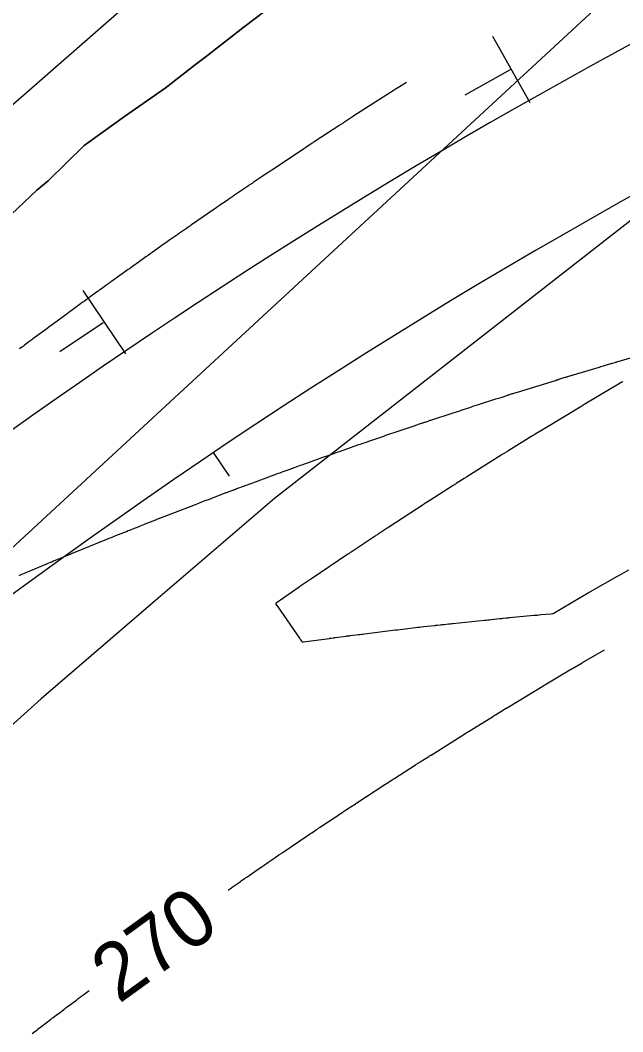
# Model space of a CAD drawing. Extents: x 1710723 to 1713003, y 548603 to 551142.
# Drawn here: x 1711041.1 to 1711104.3, y 549044.7 to 549150.8 of the extents above; entities that cross this region are included whole.
import ezdxf

# ---------------------------------------------------------------- set-up
doc = ezdxf.new("R2010")
doc.units = 0
for name, color, linetype in [('R_Contour Annot', 7, 'Continuous'), ('R_Contours', 7, 'Continuous'), ('R_Horz Alg', 7, 'Continuous'), ('R_Horz Alg Annot', 7, 'Continuous'), ('R_MOT', 7, 'Continuous'), ('R_No Plot', 7, 'Continuous'), ('R_Striping', 7, 'Continuous')]:
    doc.layers.add(name, color=color, linetype=linetype)

msp = doc.modelspace()

# ---------------------------------------------------------------- linework, layer by layer
at = {"layer": 'R_Contours'}
for points in [[(1711081.57, 549144.32), (1711080.41, 549143.58), (1711080.37, 549143.56), (1711080.28, 549143.5), (1711076.06, 549140.8), (1711076.03, 549140.78), (1711075.92, 549140.71), (1711074.98, 549140.1), (1711074.94, 549140.07), (1711074.9, 549140.04), (1711074.86, 549140.02), (1711074.82, 549139.99), (1711074.57, 549139.83), (1711074.49, 549139.78), (1711071.9, 549138.08), (1711071.81, 549138.02), (1711071.72, 549137.96), (1711071.63, 549137.9), (1711071.54, 549137.84), (1711071.18, 549137.61), (1711071.01, 549137.49), (1711070.83, 549137.37), (1711067.51, 549135.16), (1711067.47, 549135.13), (1711067.43, 549135.11), (1711067.38, 549135.08), (1711067.34, 549135.05), (1711067.13, 549134.91), (1711067, 549134.82), (1711066.45, 549134.45), (1711066.34, 549134.38), (1711066.24, 549134.31), (1711066.13, 549134.24), (1711066.03, 549134.16), (1711065.5, 549133.81), (1711065.38, 549133.72), (1711065.26, 549133.64), (1711065.13, 549133.56), (1711065.01, 549133.47), (1711063.54, 549132.48), (1711063.35, 549132.35), (1711063.16, 549132.22), (1711062.96, 549132.08), (1711062.77, 549131.95), (1711062.01, 549131.43), (1711061.82, 549131.3), (1711061.63, 549131.17), (1711061.44, 549131.04), (1711061.25, 549130.91), (1711059.03, 549129.37), (1711058.97, 549129.33), (1711058.91, 549129.29), (1711058.85, 549129.25), (1711058.79, 549129.21), (1711058.49, 549129), (1711058.31, 549128.87), (1711057.86, 549128.56), (1711057.77, 549128.5), (1711057.68, 549128.43), (1711057.58, 549128.37), (1711057.49, 549128.3), (1711056.77, 549127.8), (1711056.62, 549127.69), (1711056.47, 549127.59), (1711056.32, 549127.48), (1711056.17, 549127.37), (1711055.13, 549126.65), (1711054.91, 549126.49), (1711054.69, 549126.33), (1711054.47, 549126.17), (1711054.25, 549126.02), (1711053.3, 549125.34), (1711053.07, 549125.18), (1711052.84, 549125.01), (1711052.61, 549124.85), (1711052.38, 549124.68), (1711050.65, 549123.45), (1711050.57, 549123.39), (1711050.49, 549123.34), (1711050.42, 549123.28), (1711050.34, 549123.23), (1711050.03, 549123), (1711049.87, 549122.89), (1711049.72, 549122.78), (1711049.38, 549122.54), (1711049.3, 549122.48), (1711049.22, 549122.42), (1711049.14, 549122.36), (1711049.05, 549122.3), (1711048.11, 549121.61), (1711047.93, 549121.48), (1711047.75, 549121.35), (1711047.57, 549121.22), (1711047.39, 549121.09), (1711046.68, 549120.57), (1711046.5, 549120.44), (1711046.33, 549120.31), (1711046.15, 549120.18), (1711045.97, 549120.05), (1711044.55, 549119), (1711044.31, 549118.82), (1711044.07, 549118.65), (1711043.84, 549118.47), (1711043.6, 549118.3), (1711042.39, 549117.41), (1711042.29, 549117.33), (1711042.18, 549117.25), (1711042.08, 549117.17), (1711041.97, 549117.1), (1711041.47, 549116.72), (1711041.35, 549116.63), (1711041.23, 549116.54), (1711040.98, 549116.36)], [(1711040.96, 549092.6), (1711041.15, 549092.68), (1711041.33, 549092.76), (1711041.52, 549092.84), (1711043.66, 549093.74), (1711043.73, 549093.76), (1711043.79, 549093.79), (1711043.85, 549093.82), (1711043.92, 549093.84), (1711044.24, 549093.98), (1711044.3, 549094), (1711044.36, 549094.03), (1711044.48, 549094.08), (1711044.5, 549094.09), (1711044.53, 549094.1), (1711044.56, 549094.11), (1711044.59, 549094.13), (1711045.88, 549094.66), (1711046.28, 549094.82), (1711046.35, 549094.85), (1711046.42, 549094.88), (1711046.48, 549094.91), (1711046.55, 549094.93), (1711050.14, 549096.39), (1711050.38, 549096.49), (1711050.62, 549096.59), (1711050.86, 549096.68), (1711051.1, 549096.78), (1711052.21, 549097.22), (1711052.37, 549097.29), (1711052.54, 549097.35), (1711052.7, 549097.42), (1711052.86, 549097.48), (1711053.52, 549097.74), (1711053.69, 549097.81), (1711053.85, 549097.87), (1711054.01, 549097.94), (1711054.18, 549098), (1711055.28, 549098.44), (1711055.31, 549098.45), (1711055.37, 549098.47), (1711055.39, 549098.48), (1711055.57, 549098.55), (1711055.6, 549098.56), (1711055.63, 549098.57), (1711055.66, 549098.59), (1711055.7, 549098.6), (1711059.45, 549100.05), (1711059.79, 549100.18), (1711060.12, 549100.31), (1711060.46, 549100.44), (1711060.8, 549100.57), (1711062.67, 549101.28), (1711062.75, 549101.31), (1711062.83, 549101.34), (1711062.9, 549101.37), (1711062.98, 549101.39), (1711063.36, 549101.54), (1711063.39, 549101.55), (1711063.43, 549101.56), (1711063.47, 549101.58), (1711063.5, 549101.59), (1711063.65, 549101.64), (1711063.68, 549101.66), (1711063.72, 549101.67), (1711063.76, 549101.69), (1711063.79, 549101.7), (1711064.6, 549102), (1711064.74, 549102.05), (1711064.89, 549102.11), (1711065.03, 549102.16), (1711065.18, 549102.22), (1711067.98, 549103.25), (1711068.15, 549103.31), (1711068.32, 549103.37), (1711068.48, 549103.43), (1711068.65, 549103.49), (1711069.38, 549103.76), (1711069.52, 549103.81), (1711069.66, 549103.86), (1711069.79, 549103.91), (1711069.93, 549103.96), (1711070.48, 549104.15), (1711070.62, 549104.2), (1711070.76, 549104.25), (1711070.9, 549104.3), (1711071.03, 549104.35), (1711072.82, 549104.99), (1711072.93, 549105.03), (1711073.04, 549105.07), (1711073.14, 549105.11), (1711073.25, 549105.15), (1711073.77, 549105.33), (1711073.83, 549105.35), (1711073.9, 549105.38), (1711073.96, 549105.4), (1711074.03, 549105.42), (1711074.3, 549105.52), (1711074.43, 549105.56), (1711074.56, 549105.61), (1711076.59, 549106.32), (1711076.85, 549106.41), (1711077.11, 549106.5), (1711077.38, 549106.59), (1711077.64, 549106.68), (1711078.78, 549107.08), (1711079, 549107.15), (1711079.21, 549107.22), (1711079.42, 549107.3), (1711079.64, 549107.37), (1711080.49, 549107.66), (1711080.7, 549107.74), (1711080.91, 549107.81), (1711081.13, 549107.88), (1711081.34, 549107.95), (1711082.48, 549108.34), (1711082.57, 549108.37), (1711082.67, 549108.4), (1711082.76, 549108.43), (1711082.85, 549108.46), (1711083.25, 549108.59), (1711083.33, 549108.62), (1711083.4, 549108.64), (1711083.48, 549108.67), (1711083.55, 549108.69), (1711083.85, 549108.79), (1711083.92, 549108.82), (1711084, 549108.84), (1711084.07, 549108.87), (1711084.14, 549108.89), (1711086.5, 549109.66), (1711086.73, 549109.73), (1711086.95, 549109.81), (1711087.18, 549109.88), (1711087.41, 549109.96), (1711088.33, 549110.26), (1711088.56, 549110.34), (1711088.79, 549110.41), (1711089.02, 549110.49), (1711089.24, 549110.56), (1711090.97, 549111.11), (1711091.1, 549111.15), (1711091.24, 549111.19), (1711091.37, 549111.24), (1711091.51, 549111.28), (1711092.23, 549111.51), (1711092.27, 549111.53), (1711092.32, 549111.54), (1711092.36, 549111.56), (1711092.4, 549111.57), (1711092.58, 549111.63), (1711092.63, 549111.64), (1711092.67, 549111.65), (1711092.71, 549111.67), (1711092.76, 549111.68), (1711093.35, 549111.87), (1711093.47, 549111.9), (1711093.58, 549111.94), (1711093.69, 549111.97), (1711093.81, 549112.01), (1711097.23, 549113.06), (1711097.34, 549113.1), (1711097.46, 549113.13), (1711097.57, 549113.17), (1711097.69, 549113.21), (1711098.23, 549113.38), (1711098.3, 549113.4), (1711098.38, 549113.42), (1711098.45, 549113.44), (1711098.53, 549113.47), (1711098.83, 549113.56), (1711098.9, 549113.58), (1711098.97, 549113.6), (1711099.05, 549113.63), (1711099.12, 549113.65), (1711101.71, 549114.42), (1711101.85, 549114.46), (1711101.98, 549114.5), (1711102.12, 549114.54), (1711102.25, 549114.59), (1711103.04, 549114.82), (1711103.09, 549114.83), (1711103.17, 549114.86), (1711103.21, 549114.87), (1711103.47, 549114.95), (1711103.52, 549114.96), (1711103.57, 549114.97), (1711103.62, 549114.99), (1711103.67, 549115), (1711107.98, 549116.25)], [(1711104.3, 549112.94), (1711104.24, 549112.9), (1711104.17, 549112.86), (1711103.3, 549112.35), (1711103.26, 549112.33), (1711103.22, 549112.3), (1711100.31, 549110.57), (1711100.23, 549110.52), (1711100.14, 549110.47), (1711100.06, 549110.42), (1711099.97, 549110.37), (1711096.09, 549108.02), (1711096.04, 549107.99), (1711096, 549107.96), (1711095.95, 549107.93), (1711095.91, 549107.91), (1711095.09, 549107.41), (1711095, 549107.35), (1711094.91, 549107.3), (1711094.82, 549107.24), (1711094.73, 549107.19), (1711092.34, 549105.71), (1711092.11, 549105.57), (1711091.88, 549105.42), (1711091.64, 549105.28), (1711091.41, 549105.13), (1711087.91, 549102.93), (1711087.84, 549102.89), (1711087.78, 549102.85), (1711087.71, 549102.81), (1711087.64, 549102.77), (1711086.79, 549102.23), (1711086.72, 549102.18), (1711086.64, 549102.13), (1711086.56, 549102.08), (1711086.49, 549102.03), (1711084.05, 549100.47), (1711083.87, 549100.36), (1711083.7, 549100.24), (1711083.52, 549100.13), (1711083.34, 549100.01), (1711079.72, 549097.66), (1711079.68, 549097.63), (1711079.64, 549097.6), (1711079.6, 549097.58), (1711079.56, 549097.55), (1711078.63, 549096.94), (1711078.54, 549096.88), (1711078.46, 549096.83), (1711078.37, 549096.77), (1711078.29, 549096.71), (1711075.77, 549095.04), (1711075.69, 549094.99), (1711075.6, 549094.93), (1711075.52, 549094.87), (1711075.43, 549094.81), (1711071.61, 549092.24), (1711071.59, 549092.22), (1711071.56, 549092.2), (1711070.41, 549091.42), (1711070.37, 549091.39), (1711070.33, 549091.36), (1711067.92, 549089.7), (1711067.89, 549089.68), (1711067.87, 549089.64), (1711067.87, 549089.61), (1711067.89, 549089.57), (1711068.05, 549089.34), (1711068.08, 549089.3), (1711070.35, 549086.01), (1711070.38, 549085.97), (1711070.41, 549085.93), (1711070.43, 549085.89), (1711070.46, 549085.85), (1711070.57, 549085.68), (1711070.6, 549085.65), (1711070.64, 549085.63), (1711070.68, 549085.61), (1711070.73, 549085.62), (1711073.49, 549085.99), (1711073.54, 549086), (1711073.59, 549086.01), (1711073.64, 549086.01), (1711073.69, 549086.02), (1711073.9, 549086.05), (1711073.95, 549086.05), (1711074, 549086.06), (1711074.05, 549086.07), (1711074.1, 549086.07), (1711075.27, 549086.23), (1711075.3, 549086.23), (1711075.34, 549086.24), (1711075.37, 549086.24), (1711075.41, 549086.24), (1711075.55, 549086.26), (1711075.59, 549086.27), (1711075.62, 549086.27), (1711075.66, 549086.28), (1711075.69, 549086.28), (1711076.55, 549086.38), (1711076.71, 549086.4), (1711076.87, 549086.42), (1711077.02, 549086.44), (1711077.18, 549086.46), (1711080.42, 549086.87), (1711080.68, 549086.9), (1711080.93, 549086.93), (1711081.18, 549086.96), (1711081.43, 549086.99), (1711082.52, 549087.12), (1711082.73, 549087.15), (1711082.95, 549087.17), (1711083.17, 549087.2), (1711083.38, 549087.22), (1711084.51, 549087.34), (1711084.6, 549087.35), (1711084.68, 549087.36), (1711084.77, 549087.37), (1711084.85, 549087.38), (1711085.2, 549087.42), (1711085.28, 549087.43), (1711085.37, 549087.44), (1711085.46, 549087.45), (1711085.54, 549087.46), (1711086.01, 549087.51), (1711086.12, 549087.52), (1711086.22, 549087.53), (1711086.33, 549087.54), (1711086.44, 549087.55), (1711089.77, 549087.9), (1711089.95, 549087.91), (1711090.12, 549087.93), (1711090.29, 549087.95), (1711090.47, 549087.97), (1711091.33, 549088.06), (1711091.42, 549088.07), (1711091.51, 549088.08), (1711091.6, 549088.09), (1711091.68, 549088.1), (1711092.03, 549088.14), (1711092.12, 549088.15), (1711092.21, 549088.15), (1711092.3, 549088.16), (1711092.39, 549088.17), (1711094.95, 549088.41), (1711095.14, 549088.43), (1711095.32, 549088.44), (1711095.5, 549088.46), (1711095.68, 549088.48), (1711096.77, 549088.58), (1711096.78, 549088.58), (1711096.91, 549088.59), (1711096.93, 549088.59), (1711096.95, 549088.6), (1711096.97, 549088.6), (1711096.99, 549088.61), (1711100.77, 549090.82), (1711100.86, 549090.87), (1711100.89, 549090.89), (1711100.91, 549090.9), (1711103.74, 549092.52), (1711103.86, 549092.59), (1711103.9, 549092.61), (1711103.92, 549092.62), (1711104.91, 549093.19)], [(1711062.89, 549059.6), (1711062.91, 549059.61), (1711063.01, 549059.68), (1711063.11, 549059.75), (1711063.21, 549059.82), (1711063.31, 549059.89), (1711064.02, 549060.39), (1711064.16, 549060.48), (1711064.29, 549060.57), (1711064.56, 549060.76), (1711064.63, 549060.81), (1711064.69, 549060.85), (1711064.76, 549060.9), (1711064.83, 549060.95), (1711066.25, 549061.93), (1711066.35, 549061.99), (1711066.45, 549062.06), (1711066.55, 549062.13), (1711066.65, 549062.2), (1711067.05, 549062.48), (1711067.15, 549062.55), (1711067.25, 549062.62), (1711067.35, 549062.69), (1711067.45, 549062.75), (1711068.06, 549063.17), (1711068.2, 549063.27), (1711068.44, 549063.43), (1711068.49, 549063.46), (1711068.54, 549063.49), (1711068.59, 549063.53), (1711068.63, 549063.56), (1711071.15, 549065.26), (1711071.28, 549065.34), (1711071.4, 549065.43), (1711071.53, 549065.51), (1711071.65, 549065.59), (1711072.15, 549065.93), (1711072.28, 549066.02), (1711072.4, 549066.1), (1711072.53, 549066.19), (1711072.66, 549066.27), (1711074.26, 549067.33), (1711074.42, 549067.44), (1711074.57, 549067.54), (1711074.89, 549067.75), (1711074.97, 549067.81), (1711075.05, 549067.86), (1711075.13, 549067.91), (1711075.2, 549067.96), (1711075.94, 549068.45), (1711076.08, 549068.54), (1711076.22, 549068.63), (1711076.26, 549068.65), (1711076.29, 549068.68), (1711076.33, 549068.7), (1711076.36, 549068.72), (1711079.31, 549070.65), (1711079.49, 549070.76), (1711079.67, 549070.88), (1711080.02, 549071.11), (1711080.11, 549071.16), (1711080.2, 549071.22), (1711080.29, 549071.28), (1711080.37, 549071.33), (1711082.43, 549072.65), (1711082.58, 549072.75), (1711082.82, 549072.9), (1711082.87, 549072.94), (1711082.92, 549072.97), (1711082.97, 549073), (1711083.02, 549073.03), (1711083.93, 549073.61), (1711084.01, 549073.66), (1711084.08, 549073.71), (1711084.12, 549073.73), (1711084.16, 549073.75), (1711087.69, 549075.97), (1711087.84, 549076.07), (1711087.99, 549076.16), (1711088.03, 549076.18), (1711088.07, 549076.21), (1711088.11, 549076.23), (1711088.15, 549076.25), (1711090.71, 549077.84), (1711090.77, 549077.88), (1711090.87, 549077.94), (1711090.89, 549077.95), (1711090.94, 549077.98), (1711091.99, 549078.63), (1711092.03, 549078.65), (1711092.07, 549078.68), (1711092.24, 549078.77), (1711096, 549081.05), (1711096.03, 549081.07), (1711096.1, 549081.11), (1711098.9, 549082.78), (1711098.93, 549082.79), (1711100.01, 549083.43), (1711100.06, 549083.46), (1711102.35, 549084.8)], [(1711042.32, 549044.53), (1711042.82, 549044.91), (1711042.95, 549045.01), (1711043.07, 549045.11), (1711043.2, 549045.2), (1711043.32, 549045.3), (1711044.24, 549046), (1711044.31, 549046.05), (1711044.39, 549046.11), (1711044.46, 549046.17), (1711044.53, 549046.22), (1711044.83, 549046.45), (1711044.98, 549046.56), (1711045.13, 549046.67), (1711045.58, 549047.02), (1711045.68, 549047.09), (1711045.78, 549047.17), (1711045.89, 549047.25), (1711045.99, 549047.32), (1711046.95, 549048.04), (1711047.14, 549048.19), (1711047.33, 549048.33), (1711047.53, 549048.48), (1711047.72, 549048.62), (1711048.3, 549049.05)]]:
    msp.add_lwpolyline(points, dxfattribs=at)
at = {"layer": 'R_Horz Alg'}
msp.add_arc((1711398.54, 548605.45), 603.11, 90.64281, 132.74131, dxfattribs=at)
at = {"layer": 'R_Horz Alg Annot'}
msp.add_line((1710989.21, 549048.39), (1711159.68, 549205.92), dxfattribs=at)
msp.add_lwpolyline([(1711063.03, 549103.01), (1711061.35, 549105.5)], dxfattribs=at)
at = {"layer": 'R_MOT'}
for p, q in [((1711090.62, 549149.18), (1711094.53, 549142.21)), ((1711092.46, 549145.66), (1711087.7, 549142.98)), ((1711047.62, 549122.48), (1711052.09, 549115.84)), ((1711049.75, 549119.11), (1711045.22, 549116.06))]:
    msp.add_line(p, q, dxfattribs=at)
msp.add_lwpolyline([(1711067.88, 549152.68), (1711064.55, 549150.14), (1711060.41, 549146.94), (1711059.44, 549146.19), (1711056.28, 549143.72), (1711052, 549140.74), (1711050.87, 549139.95), (1711047.76, 549137.72), (1711044, 549133.98), (1711042.81, 549133), (1711040.11, 549130.46), (1711036.33, 549126.81), (1711035.11, 549125.61), (1711031.93, 549122.45)], dxfattribs=at)
msp.add_arc((1711398.54, 548605.45), 617.11, 108.54528, 126.36568, dxfattribs=at)
at = {"layer": 'R_No Plot'}
msp.add_line((1710723.07, 548865.06), (1711226.5, 549304.64), dxfattribs=at)
for points in [[(1711265.88, 549232.81), (1711277.23, 549233.43), (1711294.61, 549232.47), (1711306.31, 549234.47), (1711308.15, 549221.56), (1711270.83, 549215.07), (1711235.54, 549206.55), (1711200.34, 549195.8), (1711202.96, 549188.6), (1711171.09, 549176.56), (1711151.59, 549163.73), (1711132.09, 549150.89), (1711116, 549138.34), (1711099.91, 549125.79), (1711083.82, 549113.23), (1711067.73, 549100.68), (1711055.49, 549090.16), (1711043.26, 549079.63), (1711026.58, 549064.63), (1711009.91, 549049.63), (1710993.23, 549034.63), (1710976.56, 549019.63)], [(1711265.68, 549233.34), (1711277.23, 549233.43), (1711298.42, 549234.46), (1711306.31, 549234.47), (1711308.06, 549222.25), (1711270.83, 549215.07), (1711226.7, 549204.73), (1711200.34, 549195.8), (1711202.96, 549188.6), (1711171.09, 549176.56), (1711151.59, 549163.73), (1711132.09, 549150.89), (1711116, 549138.34), (1711099.91, 549125.79), (1711083.82, 549113.23), (1711067.73, 549100.68), (1711055.49, 549090.16), (1711043.26, 549079.63), (1711026.58, 549064.63), (1711009.91, 549049.63), (1710993.23, 549034.63), (1710976.56, 549019.63)], [(1711031.93, 549122.45), (1711035.11, 549125.61), (1711036.33, 549126.81), (1711040.11, 549130.46), (1711042.81, 549133), (1711044, 549133.98), (1711047.76, 549137.72), (1711050.87, 549139.95), (1711052, 549140.74), (1711056.28, 549143.72), (1711059.44, 549146.19), (1711060.41, 549146.94), (1711064.55, 549150.14), (1711067.88, 549152.68)]]:
    msp.add_lwpolyline(points, dxfattribs=at)
at = {"layer": 'R_Striping'}
msp.add_arc((1711398.54, 548605.45), 603.11, 90.64281, 132.74131, dxfattribs=at)

# ---------------------------------------------------------------- texts
at = {"layer": 'R_Contour Annot'}
msp.add_text('270', height=6, rotation=35.8568, dxfattribs=at).set_placement((1711051.4, 549047.59))

doc.saveas('drawing.dxf')
